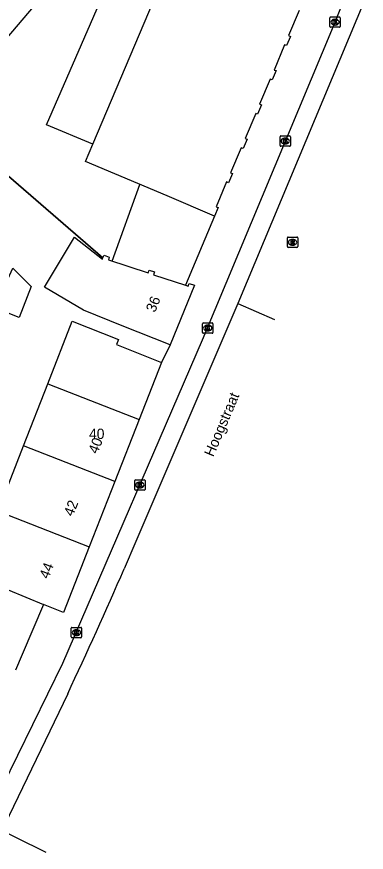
# Model space of a CAD drawing. Extents: x 160107 to 160928, y 382056 to 382918.
# Drawn here: x 160879 to 160912.9, y 382746.8 to 382827.7 of the extents above; entities that cross this region are included whole.
import ezdxf

# ---------------------------------------------------------------- set-up
doc = ezdxf.new("R2010")
doc.units = 0
for name, color, linetype in [('IMGEO_Hek', 7, 'Continuous'), ('IMGEO_Kolk', 7, 'Continuous'), ('IMGEO_Muur', 7, 'Continuous'), ('IMGEO_Openbare_ruimte_label', 7, 'Continuous'), ('IMGEO_Pand', 7, 'Continuous'), ('IMGEO_Pand_nummerreeks', 7, 'Continuous'), ('IMGEO_Rijbaan_lokaal_gesloten', 7, 'Continuous'), ('IMGEO_Rijbaan_lokaal_open', 7, 'Continuous'), ('IMGEO_Rioolput', 7, 'Continuous'), ('IMGEO_Voetpad_open', 7, 'Continuous')]:
    doc.layers.add(name, color=color, linetype=linetype)

msp = doc.modelspace()

# ---------------------------------------------------------------- linework, layer by layer
at = {"layer": 'IMGEO_Hek'}
msp.add_lwpolyline([(160888.264, 382804.05), (160890.942, 382811.468)], dxfattribs=at)
at = {"layer": 'IMGEO_Kolk'}
for p, q in [((160909.333, 382826.751), (160909.333, 382827.603)), ((160909.408, 382827.677), (160910.26, 382827.677)), ((160910.334, 382827.603), (160910.334, 382826.751)), ((160909.844, 382826.897), (160909.819, 382826.897)), ((160909.821, 382827.457), (160909.846, 382827.457)), ((160910.26, 382826.677), (160909.408, 382826.677)), ((160904.513, 382815.238), (160904.513, 382816.09)), ((160904.588, 382816.164), (160905.44, 382816.164)), ((160905.024, 382815.384), (160904.999, 382815.384)), ((160905.001, 382815.944), (160905.026, 382815.944)), ((160905.514, 382816.09), (160905.514, 382815.238)), ((160905.44, 382815.164), (160904.588, 382815.164)), ((160897.011, 382797.135), (160897.011, 382797.987)), ((160897.086, 382798.061), (160897.938, 382798.061)), ((160897.499, 382797.841), (160897.524, 382797.841)), ((160898.012, 382797.987), (160898.012, 382797.135)), ((160897.938, 382797.061), (160897.086, 382797.061)), ((160897.522, 382797.281), (160897.497, 382797.281)), ((160890.438, 382781.95), (160890.438, 382782.802)), ((160890.513, 382782.876), (160891.365, 382782.876)), ((160890.926, 382782.656), (160890.951, 382782.656)), ((160891.439, 382782.802), (160891.439, 382781.95)), ((160891.365, 382781.876), (160890.513, 382781.876)), ((160890.949, 382782.096), (160890.924, 382782.096)), ((160884.29, 382767.657), (160884.29, 382768.509)), ((160884.365, 382768.583), (160885.217, 382768.583)), ((160885.291, 382768.509), (160885.291, 382767.657)), ((160884.801, 382767.803), (160884.776, 382767.803)), ((160884.778, 382768.363), (160884.803, 382768.363)), ((160885.217, 382767.583), (160884.365, 382767.583))]:
    msp.add_line(p, q, dxfattribs=at)
for points in [[(160909.333, 382826.751), (160909.333, 382827.603)], [(160909.408, 382827.677), (160910.26, 382827.677)], [(160910.334, 382827.603), (160910.334, 382826.751)], [(160909.654, 382827.377), (160909.777, 382827.377), (160909.777, 382827.226), (160909.907, 382827.377), (160910.071, 382827.377), (160909.925, 382827.226), (160910.078, 382826.977), (160909.926, 382826.977), (160909.841, 382827.141), (160909.777, 382827.074), (160909.777, 382826.977), (160909.654, 382826.977), (160909.654, 382827.377)], [(160910.26, 382826.677), (160909.408, 382826.677)], [(160904.513, 382815.238), (160904.513, 382816.09)], [(160904.588, 382816.164), (160905.44, 382816.164)], [(160904.834, 382815.864), (160904.957, 382815.864), (160904.957, 382815.713), (160905.087, 382815.864), (160905.251, 382815.864), (160905.105, 382815.713), (160905.258, 382815.464), (160905.106, 382815.464), (160905.021, 382815.628), (160904.957, 382815.561), (160904.957, 382815.464), (160904.834, 382815.464), (160904.834, 382815.864)], [(160905.514, 382816.09), (160905.514, 382815.238)], [(160905.44, 382815.164), (160904.588, 382815.164)], [(160897.011, 382797.135), (160897.011, 382797.987)], [(160897.086, 382798.061), (160897.938, 382798.061)], [(160897.332, 382797.761), (160897.455, 382797.761), (160897.455, 382797.61), (160897.585, 382797.761), (160897.749, 382797.761), (160897.603, 382797.61), (160897.756, 382797.361), (160897.604, 382797.361), (160897.519, 382797.525), (160897.455, 382797.458), (160897.455, 382797.361), (160897.332, 382797.361), (160897.332, 382797.761)], [(160898.012, 382797.987), (160898.012, 382797.135)], [(160897.938, 382797.061), (160897.086, 382797.061)], [(160890.438, 382781.95), (160890.438, 382782.802)], [(160890.513, 382782.876), (160891.365, 382782.876)], [(160890.759, 382782.576), (160890.882, 382782.576), (160890.882, 382782.425), (160891.012, 382782.576), (160891.176, 382782.576), (160891.03, 382782.425), (160891.183, 382782.176), (160891.031, 382782.176), (160890.946, 382782.34), (160890.882, 382782.273), (160890.882, 382782.176), (160890.759, 382782.176), (160890.759, 382782.576)], [(160891.439, 382782.802), (160891.439, 382781.95)], [(160891.365, 382781.876), (160890.513, 382781.876)], [(160884.29, 382767.657), (160884.29, 382768.509)], [(160884.365, 382768.583), (160885.217, 382768.583)], [(160885.291, 382768.509), (160885.291, 382767.657)], [(160884.611, 382768.283), (160884.734, 382768.283), (160884.734, 382768.132), (160884.864, 382768.283), (160885.028, 382768.283), (160884.882, 382768.132), (160885.035, 382767.883), (160884.883, 382767.883), (160884.798, 382768.047), (160884.734, 382767.98), (160884.734, 382767.883), (160884.611, 382767.883), (160884.611, 382768.283)], [(160885.217, 382767.583), (160884.365, 382767.583)]]:
    msp.add_lwpolyline(points, dxfattribs=at)
for centre, start, end in [((160909.41, 382827.601), 91.55205, 178.44795), ((160909.41, 382827.601), 91.55205, 178.44795), ((160910.258, 382827.601), 1.55205, 88.44795), ((160910.258, 382827.601), 1.55205, 88.44795), ((160909.41, 382826.753), 181.55205, 268.44795), ((160909.41, 382826.753), 181.55205, 268.44795), ((160910.258, 382826.753), 271.55205, 358.44795), ((160910.258, 382826.753), 271.55205, 358.44795), ((160904.59, 382816.088), 91.55205, 178.44795), ((160904.59, 382816.088), 91.55205, 178.44795), ((160905.438, 382816.088), 1.55205, 88.44795), ((160905.438, 382816.088), 1.55205, 88.44795), ((160904.59, 382815.24), 181.55205, 268.44795), ((160904.59, 382815.24), 181.55205, 268.44795), ((160905.438, 382815.24), 271.55205, 358.44795), ((160905.438, 382815.24), 271.55205, 358.44795), ((160897.088, 382797.985), 91.55205, 178.44795), ((160897.088, 382797.985), 91.55205, 178.44795), ((160897.936, 382797.985), 1.55205, 88.44795), ((160897.936, 382797.985), 1.55205, 88.44795), ((160897.088, 382797.137), 181.55205, 268.44795), ((160897.088, 382797.137), 181.55205, 268.44795), ((160897.936, 382797.137), 271.55205, 358.44795), ((160897.936, 382797.137), 271.55205, 358.44795), ((160890.515, 382782.8), 91.55205, 178.44795), ((160890.515, 382782.8), 91.55205, 178.44795), ((160891.363, 382782.8), 1.55205, 88.44795), ((160891.363, 382782.8), 1.55205, 88.44795), ((160890.515, 382781.952), 181.55205, 268.44795), ((160890.515, 382781.952), 181.55205, 268.44795), ((160891.363, 382781.952), 271.55205, 358.44795), ((160891.363, 382781.952), 271.55205, 358.44795), ((160884.367, 382768.507), 91.55205, 178.44795), ((160884.367, 382768.507), 91.55205, 178.44795), ((160885.215, 382768.507), 1.55205, 88.44795), ((160885.215, 382768.507), 1.55205, 88.44795), ((160884.367, 382767.659), 181.55205, 268.44795), ((160884.367, 382767.659), 181.55205, 268.44795), ((160885.215, 382767.659), 271.55205, 358.44795), ((160885.215, 382767.659), 271.55205, 358.44795)]:
    msp.add_arc(centre, 0.0765, start, end, dxfattribs=at)
for centre, major_axis, ratio, start_param, end_param in [((160909.82, 382827.177), (-0.387, 0.002), 0.722429, 4.712389, 7.853982), ((160909.845, 382827.177), (-0.39, 0.002), 0.717154, 1.570796, 4.712389), ((160905, 382815.664), (-0.387, 0.002), 0.722429, 4.712389, 7.853982), ((160905.025, 382815.664), (-0.39, 0.002), 0.717154, 1.570796, 4.712389), ((160897.498, 382797.561), (-0.387, 0.002), 0.722429, 4.712389, 7.853982), ((160897.523, 382797.561), (-0.39, 0.002), 0.717154, 1.570796, 4.712389), ((160890.925, 382782.376), (-0.387, 0.002), 0.722429, 4.712389, 7.853982), ((160890.95, 382782.376), (-0.39, 0.002), 0.717154, 1.570796, 4.712389), ((160884.777, 382768.083), (-0.387, 0.002), 0.722429, 4.712389, 7.853982), ((160884.802, 382768.083), (-0.39, 0.002), 0.717154, 1.570796, 4.712389)]:
    msp.add_ellipse(centre, major_axis=major_axis, ratio=ratio, start_param=start_param, end_param=end_param, dxfattribs=at)
at = {"layer": 'IMGEO_Muur'}
msp.add_lwpolyline([(160872.674, 382817.052), (160887.366, 382804.346)], dxfattribs=at)
at = {"layer": 'IMGEO_Pand'}
for points in [[(160886.391, 382815.35), (160894.957, 382835.628)], [(160906.374, 382828.29), (160905.333, 382825.874), (160905.528, 382825.799), (160905.146, 382824.901), (160904.956, 382824.973), (160903.93, 382822.543), (160904.126, 382822.484), (160903.743, 382821.585), (160903.55, 382821.657), (160902.523, 382819.225), (160902.722, 382819.16), (160902.343, 382818.261), (160902.153, 382818.327), (160901.119, 382815.928), (160901.315, 382815.851), (160900.941, 382814.951), (160900.743, 382815.009), (160899.722, 382812.598), (160899.913, 382812.526), (160899.523, 382811.632), (160899.34, 382811.704), (160898.327, 382809.298), (160898.513, 382809.22), (160898.179, 382808.41)], [(160898.179, 382808.41), (160893.574, 382810.356), (160885.688, 382813.687), (160886.391, 382815.35)], [(160893.861, 382795.927), (160889.222, 382797.792), (160885.476, 382799.297), (160881.699, 382801.511), (160884.614, 382806.378), (160887.321, 382804.235), (160887.366, 382804.346)], [(160887.366, 382804.346), (160887.47, 382804.606), (160887.971, 382804.441), (160887.884, 382804.176), (160891.739, 382802.902), (160891.826, 382803.167), (160892.339, 382802.997), (160892.252, 382802.732), (160895.357, 382801.706)], [(160879.249, 382798.573), (160876.85, 382799.536), (160878.645, 382803.346), (160880.423, 382801.592), (160879.249, 382798.573)], [(160895.357, 382801.706), (160895.622, 382801.618), (160895.709, 382801.883), (160896.231, 382801.71), (160893.861, 382795.927)], [(160882.011, 382792.179), (160884.39, 382798.236), (160888.866, 382796.448), (160888.677, 382795.974), (160893.032, 382794.234)], [(160893.032, 382794.234), (160890.863, 382788.706)], [(160879.654, 382786.178), (160882.011, 382792.179)], [(160882.011, 382792.179), (160890.863, 382788.706)], [(160890.863, 382788.706), (160888.509, 382782.704)], [(160877.168, 382779.848), (160879.654, 382786.178)], [(160888.509, 382782.704), (160879.654, 382786.178)], [(160888.509, 382782.704), (160886.026, 382776.373)], [(160877.168, 382779.848), (160886.026, 382776.373)], [(160886.026, 382776.373), (160883.542, 382770.043), (160881.607, 382770.804)], [(160874.732, 382773.645), (160881.607, 382770.804)], [(160881.607, 382770.804), (160879.55, 382765.961), (160878.904, 382764.441)]]:
    msp.add_lwpolyline(points, dxfattribs=at)
at = {"layer": 'IMGEO_Rijbaan_lokaal_gesloten'}
for points in [[(160876.197, 382750.267), (160883.479, 382765.119), (160897.018, 382796.438), (160909.834, 382827.177), (160911.478, 382831.312)], [(160912.863, 382829.706), (160900.41, 382799.932)], [(160900.41, 382799.932), (160890.54, 382776.885), (160889.414, 382774.256)], [(160900.41, 382799.932), (160903.964, 382798.406)], [(160883.947, 382762.152), (160877.844, 382749.439), (160876.197, 382750.267)]]:
    msp.add_lwpolyline(points, dxfattribs=at)
msp.add_arc((160512.376, 382937.266), 410.767, 334.76647, 336.6191, dxfattribs=at)
at = {"layer": 'IMGEO_Rijbaan_lokaal_open'}
for points in [[(160855.371, 382855.843), (160882.262, 382830.641), (160875.839, 382823.088), (160846.893, 382847.344)], [(160886.391, 382815.35), (160881.889, 382817.252), (160889.866, 382835.579), (160891.359, 382834.929), (160894.957, 382835.628)], [(160887.366, 382804.346), (160872.674, 382817.052)], [(160898.179, 382808.41), (160895.357, 382801.706)], [(160875.933, 382749.726), (160881.824, 382746.815)]]:
    msp.add_lwpolyline(points, dxfattribs=at)
at = {"layer": 'IMGEO_Rioolput'}
for p, q in [((160905.225, 382805.444), (160905.225, 382806.296)), ((160905.3, 382806.37), (160906.152, 382806.37)), ((160905.713, 382806.15), (160905.738, 382806.15)), ((160906.226, 382806.296), (160906.226, 382805.444)), ((160906.152, 382805.37), (160905.3, 382805.37)), ((160905.736, 382805.59), (160905.711, 382805.59))]:
    msp.add_line(p, q, dxfattribs=at)
for points in [[(160905.225, 382805.444), (160905.225, 382806.296)], [(160905.3, 382806.37), (160906.152, 382806.37)], [(160905.814, 382806.068), (160905.562, 382806.07), (160905.562, 382805.67)], [(160905.562, 382805.67), (160905.686, 382805.67), (160905.686, 382805.832), (160905.697, 382805.832)], [(160905.74, 382805.989), (160905.686, 382805.989), (160905.686, 382805.908)], [(160905.686, 382805.908), (160905.738, 382805.908)], [(160905.744, 382805.803), (160905.815, 382805.67), (160905.955, 382805.67), (160905.89, 382805.796)], [(160906.226, 382806.296), (160906.226, 382805.444)], [(160906.152, 382805.37), (160905.3, 382805.37)]]:
    msp.add_lwpolyline(points, dxfattribs=at)
for centre, radius, start, end in [((160905.302, 382806.294), 0.0765, 91.55205, 178.44795), ((160905.302, 382806.294), 0.0765, 91.55205, 178.44795), ((160905.696, 382805.779), 0.0533, 26.02933, 88.69889), ((160905.722, 382806.097), 0.19, 274.7715, 282.96867), ((160905.746, 382805.893), 0.0964, 77.00612, 93.18647), ((160905.76, 382805.95), 0.0378, 276.66336, 79.67722), ((160905.813, 382805.958), 0.109, 350.36119, 89.41601), ((160905.811, 382805.958), 0.112, 277.58423, 350.98172), ((160905.795, 382805.743), 0.108, 29.51342, 73.79051), ((160906.15, 382806.294), 0.0765, 1.55205, 88.44795), ((160906.15, 382806.294), 0.0765, 1.55205, 88.44795), ((160905.302, 382805.446), 0.0765, 181.55205, 268.44795), ((160905.302, 382805.446), 0.0765, 181.55205, 268.44795), ((160906.15, 382805.446), 0.0765, 271.55205, 358.44795), ((160906.15, 382805.446), 0.0765, 271.55205, 358.44795)]:
    msp.add_arc(centre, radius, start, end, dxfattribs=at)
for centre, major_axis, ratio, start_param, end_param in [((160905.712, 382805.87), (-0.387, 0.002), 0.722429, 4.712389, 7.853982), ((160905.737, 382805.87), (-0.39, 0.002), 0.717154, 1.570796, 4.712389)]:
    msp.add_ellipse(centre, major_axis=major_axis, ratio=ratio, start_param=start_param, end_param=end_param, dxfattribs=at)
at = {"layer": 'IMGEO_Voetpad_open'}
msp.add_lwpolyline([(160893.861, 382795.927), (160893.032, 382794.234)], dxfattribs=at)

# ---------------------------------------------------------------- texts
at = {"layer": 'IMGEO_Openbare_ruimte_label'}
msp.add_text('Hoogstraat', height=1, rotation=67.04964, dxfattribs=at).set_placement((160898.044, 382785.031))
at = {"layer": 'IMGEO_Pand_nummerreeks'}
for s, rotation, p in [('36', 67.71511, (160892.402, 382799.01)), ('40', 68.58019, (160886.827, 382785.316)), ('42', 68.58019, (160884.452, 382779.264)), ('44', 68.58019, (160882.081, 382773.218))]:
    msp.add_text(s, height=1, rotation=rotation, dxfattribs=at).set_placement(p)
msp.add_text('40', height=1, dxfattribs=at).set_placement((160886.018, 382786.825))

doc.saveas('drawing.dxf')
